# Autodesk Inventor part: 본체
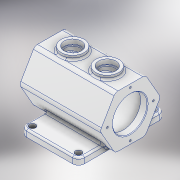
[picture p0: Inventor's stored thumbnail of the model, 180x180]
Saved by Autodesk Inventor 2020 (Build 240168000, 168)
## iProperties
Created: 2021-06
Part Number: 본체
Material: 알루미늄 6061
Document SubType Name: Modeling
Designer: Windows7
Density: 2.7 g/cm^3
Appearance: 알루미늄 - 평지
Mass: 1495.28 g
Surface Area: 1102.35 cm^2
Volume: 553.806 cm^3
Author: Windows7
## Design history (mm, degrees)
sketch "스케치1"
  geometry: L1 (-70, 0)-(70, 0); L2 (-70, 30)-(-70, 52.5); L3 (-70, 52.5)-(70, 52.5); L4 (70, 52.5)-(70, 30); L5 (70, 30)-(58, 30); L6 (58, 30)-(58, 37.5); L7 (58, 37.5)-(-58, 37.5); L8 (-58, 37.5)-(-58, 30); L9 (-58, 30)-(-70, 30); 2 further points
  constraints: 18 end point, 7 perpendicular, 2 vertical alignment, 1 coincident, 1 horizontal, 1 midpoint, 1 parallel, 1 vertical
  dimensions: "d0" = 140 distance of L1.start L1.end; "d1" = 12 distance of L8.end L2.start; "d2" = 12 distance of L4.end L5.end; "d3" = 60 diameter of L9 L1; "d4" = 75 diameter of L7 L1; "d5" = 105 diameter of L3 L1
revolve "회전1" sketch "스케치1" stored, may be unused: angle "d6" = 90 deg
fillet "모깎기1" dims "d7" = 5
chamfer "모따기1" distance "d8" = 1; stored, may be unused: second distance "d9" = 2, angle "d10" = 45 deg
sketch "스케치2"
  geometry: L1 (25.994, 45.613)-(52.499, 0.295); L2 (52.499, 0.295)-(26.505, -45.318); L3 (26.505, -45.318)-(-25.994, -45.613); L4 (-25.994, -45.613)-(-52.499, -0.295); L5 (-52.499, -0.295)-(-26.505, 45.318); L6 (-26.505, 45.318)-(25.994, 45.613); 13 further points
  constraints: 12 end point, 1 coincident, 15 other
extrude "돌출1" cut sketch "스케치2" extent not by distance; stored distance "d11" = 0; taper "d12" = 0 deg
node "작업 평면1"
sketch "스케치3"
  geometry: L1 (70, -26.505)-(70, -52.499) reference; L2 (-70, -52.499)-(-70, -26.505) reference; L3 (45, -75)-(-55, -75); L4 (-55, -75)-(-55, 75); L5 (-55, 75)-(45, 75); L6 (45, 75)-(45, -75); 2 further points
  constraints: 8 end point, 2 parallel, 1 horizontal, 1 horizontal alignment, 1 midpoint, 1 perpendicular
  dimensions: "d14" = 100 distance of L4.end L5.end; "d15" = 150 distance of L3.end L4.end; "d16" = 25 distance between parallel lines of L6 L1
extrude "돌출2" join sketch "스케치3" distance "d17" = 12; taper "d18" = 0 deg
node "작업 평면2"
sketch "스케치4"
  geometry: L1 (70, 25.994)-(70, -26.505) reference; C1 r 20 at (30, 0); C2 r 20 at (-30, 0); 1 further point
  constraints: 2 centre point, 2 horizontal alignment
  dimensions: "d20" = 40 diameter of C1; "d21" = 40 diameter of C2; "d22" = 60 distance of C1.centre C2.centre; "d23" = 40 distance from line of L1 C1.centre
extrude "돌출3" join sketch "스케치4" stored distance "d24" = 12; taper "d25" = 0 deg
sketch "스케치5"
  geometry: C1 r 20 at (0, 0) reference; C2 r 20 at (60, 0) reference; 3 further points
  constraints: 2 coincident
hole "구멍1" sketch "스케치5" at (0, 0), (60, 0) diameter "d26" = 25; stored, may be unused: countersink angle "d30" = 90 deg, drill point angle "d32" = 0 deg; dims "d27" = 6, "d28" = 30, "d29" = 8, "d31" = 52.25
sketch "스케치6"
  geometry: L1 (45.466, 26.25)-(25.272, 60.778); L2 (35.949, 72.235)-(10.052, 57.09) reference; A1 r 40 centre (45.466, 26.25) between (25.272, 60.778) and (10.938, 6.056); 1 further point
  constraints: 2 end point, 2 point on circle, 1 centre point, 1 coincident, 1 perpendicular
  dimensions: "d33" = 80 diameter of A1; "d34" = 90 deg dimension on point (45.466, 26.25) L1.end A1.end
hole "구멍2" sketch "스케치6" at (10.938, 6.056) diameter "d35" = 3.242; stored, may be unused: countersink angle "d39" = 90 deg, drill point angle "d41" = 120 deg; dims "d36" = 8, "d37" = 30, "d38" = 8, "d40" = 10
sketch "스케치7"
  geometry: L1 (26.25, -45.466)-(26.25, -85.466); C1 r 31 at (26.25, -45.466) reference; A1 r 40 centre (26.25, -45.466) between (26.25, -85.466) and (-2.034, -73.751); 1 further point
  constraints: 2 end point, 2 point on circle, 1 centre point, 1 coincident, 1 vertical
  dimensions: "d45" = 80 diameter of A1; "d46" = 45 deg dimension on point (26.25, -45.466) L1.end A1.end
hole "구멍3" sketch "스케치7" at (-2.034, -73.751) diameter "d47" = 3.242; stored, may be unused: countersink angle "d51" = 90 deg, drill point angle "d53" = 120 deg; dims "d48" = 8, "d49" = 30, "d50" = 8, "d52" = 10
fillet "모깎기2" dims "d57" = 10
fillet "모깎기3" dims "d58" = 8
sketch "스케치8"
  geometry: A1 r 10 centre (-35, -65) between (-45, -65) and (-35, -75) reference; A2 r 10 centre (45, -65) between (45, -75) and (55, -65) reference; A3 r 10 centre (45, 65) between (55, 65) and (45, 75) reference; A4 r 10 centre (-35, 65) between (-35, 75) and (-45, 65) reference; 1 further point
hole "구멍4" sketch "스케치8" at (-35, -65), (45, -65), (45, 65), (-35, 65) diameter "d59" = 11; stored, may be unused: countersink angle "d63" = 90 deg, drill point angle "d65" = 0 deg; dims "d60" = 8, "d61" = 30, "d62" = 8, "d64" = 10
fillet "모깎기4" dims "d66" = 3
fillet "모깎기5" dims "d67" = 3
chamfer "모따기2" distance "d68" = 1; stored, may be unused: second distance "d69" = 2, angle "d70" = 45 deg
sketch "스케치9"
  geometry: L1 (45, 75)-(-35, 75) reference; L2 (-45, 65)-(-45, 32.168) reference; 2 further points
  constraints: 1 other
  dimensions: "d71" = 50 distance from line of L2 point (5, 61); "d72" = 14 distance from line of point (5, 61) L1
feature "엠보싱1" sketch "스케치9" dims "d0" = 140, "d1" = 12, "d2" = 12, "d3" = 60, "d4" = 75, "d5" = 105, "d73" = 0.5, "d74" = 0
node "솔리드1"
pattern_circular "원형 패턴1" dims angle "d43" = 360 deg
pattern_circular "원형 패턴2" dims angle "d55" = 360 deg
feature "A9D066F2-1C7D-4E18-AEED-F7BC21143FA4" dims "d59" = 11, "d60" = 8, "d61" = 30, "d62" = 8, "d63" = 90 deg, "d64" = 10, "d65" = 0
other parameters: "d19" = 52.5
